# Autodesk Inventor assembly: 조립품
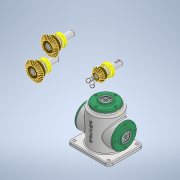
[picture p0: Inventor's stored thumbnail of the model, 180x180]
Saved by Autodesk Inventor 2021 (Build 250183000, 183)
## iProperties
Created: 2021-02
Part Number: 조립품
Document SubType Name: Assembly
Designer: mdu2-97
Author: mdu2-97
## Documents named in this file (14)
- C:\Users\mdu2-97\Desktop\710214V1002\조립품.iam
- C:\Users\mdu2-97\Desktop\710214V1002\본체.ipt
- C:\Users\mdu2-97\Desktop\710214V1002\커버.ipt
- C:\Users\mdu2-97\Desktop\710214V1002\베어링 6203.ipt
- C:\Users\mdu2-97\Desktop\710214V1002\오일 실.ipt
- 오일 실.ipt
- C:\Users\mdu2-97\Desktop\710214V1002\메인 축.ipt
- 메인 축.ipt
- C:\Users\mdu2-97\Desktop\710214V1002\키 5x5.ipt
- C:\Users\mdu2-97\Desktop\710214V1002\메인 베벨기어.ipt
- C:\Users\mdu2-97\Desktop\710214V1002\서브 축.ipt
- 서브 축.ipt
- C:\Users\mdu2-97\Desktop\710214V1002\키 4x4.ipt
- C:\Users\mdu2-97\Desktop\710214V1002\서브 베벨기어.ipt
